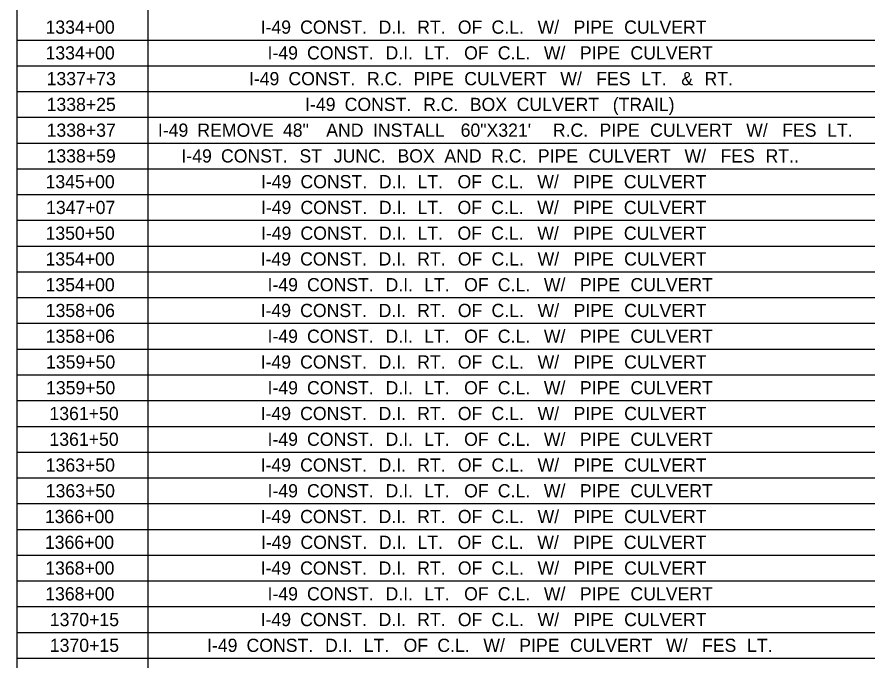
# Model space of a CAD drawing. Extents: x 1226564 to 1228153, y 151309 to 152340.
# Drawn here: x 1226563.6 to 1226838.2, y 151749.1 to 151956.8 of the extents above; entities that cross this region are included whole.
import ezdxf

# ---------------------------------------------------------------- set-up
doc = ezdxf.new("R2010")
doc.units = 0
doc.layers.add('R_Dimension', color=7, linetype='Continuous')

msp = doc.modelspace()

# ---------------------------------------------------------------- linework, layer by layer
at = {"layer": 'R_Dimension'}
for p, q in [((1226563.55, 151354.44), (1226563.55, 152160.49)), ((1226605.93, 151369.4), (1226605.93, 152160.49)), ((1226563.55, 151949.42), (1228152.75, 151949.42)), ((1226563.55, 151941.11), (1228152.75, 151941.11)), ((1226563.55, 151932.8), (1228152.75, 151932.8)), ((1226563.55, 151924.49), (1228152.75, 151924.49)), ((1226563.55, 151916.18), (1228152.75, 151916.18)), ((1226563.55, 151907.87), (1228152.75, 151907.87)), ((1226563.55, 151899.56), (1228152.75, 151899.56)), ((1226563.55, 151891.25), (1228152.75, 151891.25)), ((1226563.55, 151882.94), (1228152.75, 151882.94)), ((1226563.55, 151874.64), (1228152.75, 151874.64)), ((1226563.55, 151866.33), (1228152.75, 151866.33)), ((1226563.55, 151858.02), (1228152.75, 151858.02)), ((1226563.55, 151849.71), (1228152.75, 151849.71)), ((1226563.55, 151841.4), (1228152.75, 151841.4)), ((1226563.55, 151833.09), (1228152.75, 151833.09)), ((1226563.55, 151824.78), (1228152.75, 151824.78)), ((1226563.55, 151816.47), (1228152.75, 151816.47)), ((1226563.55, 151808.16), (1228152.75, 151808.16)), ((1226563.55, 151799.85), (1228152.75, 151799.85)), ((1226563.55, 151791.54), (1228152.75, 151791.54)), ((1226563.55, 151783.23), (1228152.75, 151783.23)), ((1226563.55, 151774.92), (1228152.75, 151774.92)), ((1226563.55, 151766.61), (1228152.75, 151766.61)), ((1226563.55, 151758.3), (1228152.75, 151758.3)), ((1226563.55, 151749.99), (1228152.75, 151749.99))]:
    msp.add_line(p, q, dxfattribs=at)

# ---------------------------------------------------------------- texts
for s, p in [('1334+00', (1226572.75, 151951.45)), ('I-49', (1226642.19, 151951.45)), (' CONST.', (1226653.36, 151951.45)), (' D.I.', (1226678.69, 151951.45)), (' RT.', (1226691.14, 151951.45)), (' OF', (1226704.26, 151951.45)), (' C.L.', (1226715.13, 151951.45)), (' W/', (1226730, 151951.45)), (' PIPE', (1226741.61, 151951.45)), (' CULVERT', (1226757.95, 151951.45)), ('1334+00', (1226572.75, 151943.14)), ('I-49', (1226644.42, 151943.14)), (' CONST.', (1226655.59, 151943.14)), (' D.I.', (1226680.93, 151943.14)), (' LT.', (1226693.37, 151943.14)), (' OF', (1226706.29, 151943.14)), (' C.L.', (1226717.16, 151943.14)), (' W/', (1226732.03, 151943.14)), (' PIPE', (1226743.64, 151943.14)), (' CULVERT', (1226759.98, 151943.14)), ('1337+73', (1226573.1, 151934.83)), ('I-49', (1226638.41, 151934.83)), (' CONST.', (1226649.59, 151934.83)), (' R.C.', (1226674.92, 151934.83)), (' PIPE', (1226689.99, 151934.83)), (' CULVERT', (1226706.33, 151934.83)), (' W/', (1226737.33, 151934.83)), (' FES', (1226748.94, 151934.83)), (' LT.', (1226763.47, 151934.83)), (' &', (1226776.39, 151934.83)), (' RT.', (1226783.87, 151934.83)), ('1338+25', (1226573.1, 151926.52)), ('I-49', (1226656.55, 151926.52)), (' CONST.', (1226667.72, 151926.52)), (' R.C.', (1226693.06, 151926.52)), (' BOX', (1226708.12, 151926.52)), (' CULVERT', (1226723.25, 151926.52)), (' (TRAIL)', (1226754.26, 151926.52)), ('1338+37', (1226573.1, 151918.21)), ('I-49', (1226609.02, 151918.21)), (' REMOVE', (1226620.19, 151918.21)), (' 48"', (1226647.81, 151918.21)), (' AND', (1226661.77, 151918.21)), (' INSTALL', (1226676.87, 151918.21)), (' 60"X321\'', (1226705.16, 151918.21)), (' R.C.', (1226734.92, 151918.21)), (' PIPE', (1226749.98, 151918.21)), (' CULVERT', (1226766.33, 151918.21)), (' W/', (1226797.33, 151918.21)), (' FES', (1226808.94, 151918.21)), (' LT.', (1226823.47, 151918.21)), ('1338+59', (1226573.08, 151909.9)), ('I-49', (1226616.63, 151909.9)), (' CONST.', (1226627.81, 151909.9)), (' ST', (1226653.14, 151909.9)), (' JUNC.', (1226664.22, 151909.9)), (' BOX', (1226684.78, 151909.9)), (' AND', (1226699.92, 151909.9)), (' R.C.', (1226715.02, 151909.9)), (' PIPE', (1226730.08, 151909.9)), (' CULVERT', (1226746.42, 151909.9)), (' W/', (1226777.43, 151909.9)), (' FES', (1226789.04, 151909.9)), (' RT..', (1226803.57, 151909.9)), ('1345+00', (1226572.75, 151901.59)), ('I-49', (1226642.29, 151901.59)), (' CONST.', (1226653.46, 151901.59)), (' D.I.', (1226678.79, 151901.59)), (' LT.', (1226691.24, 151901.59)), (' OF', (1226704.16, 151901.59)), (' C.L.', (1226715.03, 151901.59)), (' W/', (1226729.9, 151901.59)), (' PIPE', (1226741.51, 151901.59)), (' CULVERT', (1226757.85, 151901.59)), ('1347+07', (1226572.93, 151893.28)), ('I-49', (1226642.29, 151893.28)), (' CONST.', (1226653.46, 151893.28)), (' D.I.', (1226678.79, 151893.28)), (' LT.', (1226691.24, 151893.28)), (' OF', (1226704.16, 151893.28)), (' C.L.', (1226715.03, 151893.28)), (' W/', (1226729.9, 151893.28)), (' PIPE', (1226741.51, 151893.28)), (' CULVERT', (1226757.85, 151893.28)), ('1350+50', (1226572.75, 151884.97)), ('I-49', (1226642.29, 151884.97)), (' CONST.', (1226653.46, 151884.97)), (' OF', (1226704.16, 151884.97)), (' C.L.', (1226715.03, 151884.97)), (' W/', (1226729.9, 151884.97)), (' CULVERT', (1226757.85, 151884.97)), (' D.I.', (1226678.79, 151884.97)), (' LT.', (1226691.24, 151884.97)), (' PIPE', (1226741.51, 151884.97)), (' W/', (1226730, 151876.66)), ('1354+00', (1226572.75, 151876.66)), ('I-49', (1226642.19, 151876.66)), (' CONST.', (1226653.36, 151876.66)), (' D.I.', (1226678.69, 151876.66)), (' RT.', (1226691.14, 151876.66)), (' OF', (1226704.26, 151876.66)), (' C.L.', (1226715.13, 151876.66)), (' PIPE', (1226741.61, 151876.66)), (' CULVERT', (1226757.95, 151876.66)), (' W/', (1226732.03, 151868.35)), ('1354+00', (1226572.75, 151868.35)), ('I-49', (1226644.42, 151868.35)), (' CONST.', (1226655.59, 151868.35)), (' D.I.', (1226680.93, 151868.35)), (' LT.', (1226693.37, 151868.35)), (' OF', (1226706.29, 151868.35)), (' C.L.', (1226717.16, 151868.35)), (' PIPE', (1226743.64, 151868.35)), (' CULVERT', (1226759.98, 151868.35)), ('1358+06', (1226572.82, 151860.04)), ('I-49', (1226642.19, 151860.04)), (' CONST.', (1226653.36, 151860.04)), (' D.I.', (1226678.69, 151860.04)), (' RT.', (1226691.14, 151860.04)), (' OF', (1226704.26, 151860.04)), (' C.L.', (1226715.13, 151860.04)), (' W/', (1226730, 151860.04)), (' PIPE', (1226741.61, 151860.04)), (' CULVERT', (1226757.95, 151860.04)), ('1358+06', (1226572.82, 151851.73)), ('I-49', (1226644.42, 151851.73)), (' CONST.', (1226655.59, 151851.73)), (' D.I.', (1226680.93, 151851.73)), (' LT.', (1226693.37, 151851.73)), (' OF', (1226706.29, 151851.73)), (' C.L.', (1226717.16, 151851.73)), (' W/', (1226732.03, 151851.73)), (' PIPE', (1226743.64, 151851.73)), (' CULVERT', (1226759.98, 151851.73)), ('1359+50', (1226572.92, 151843.42)), ('I-49', (1226642.19, 151843.42)), (' CONST.', (1226653.36, 151843.42)), (' D.I.', (1226678.69, 151843.42)), (' RT.', (1226691.14, 151843.42)), (' OF', (1226704.26, 151843.42)), (' C.L.', (1226715.13, 151843.42)), (' W/', (1226730, 151843.42)), (' PIPE', (1226741.61, 151843.42)), (' CULVERT', (1226757.95, 151843.42)), ('1359+50', (1226572.92, 151835.11)), ('I-49', (1226644.42, 151835.11)), (' CONST.', (1226655.59, 151835.11)), (' D.I.', (1226680.93, 151835.11)), (' LT.', (1226693.37, 151835.11)), (' OF', (1226706.29, 151835.11)), (' C.L.', (1226717.16, 151835.11)), (' W/', (1226732.03, 151835.11)), (' PIPE', (1226743.64, 151835.11)), (' CULVERT', (1226759.98, 151835.11)), ('1361+50', (1226574.02, 151826.8)), ('I-49', (1226642.19, 151826.8)), (' CONST.', (1226653.36, 151826.8)), (' D.I.', (1226678.69, 151826.8)), (' RT.', (1226691.14, 151826.8)), (' OF', (1226704.26, 151826.8)), (' C.L.', (1226715.13, 151826.8)), (' W/', (1226730, 151826.8)), (' PIPE', (1226741.61, 151826.8)), (' CULVERT', (1226757.95, 151826.8)), ('1361+50', (1226574.02, 151818.49)), ('I-49', (1226644.42, 151818.49)), (' CONST.', (1226655.59, 151818.49)), (' D.I.', (1226680.93, 151818.49)), (' LT.', (1226693.37, 151818.49)), (' OF', (1226706.29, 151818.49)), (' C.L.', (1226717.16, 151818.49)), (' W/', (1226732.03, 151818.49)), (' PIPE', (1226743.64, 151818.49)), (' CULVERT', (1226759.98, 151818.49)), ('1363+50', (1226572.82, 151810.18)), ('I-49', (1226642.19, 151810.18)), (' CONST.', (1226653.36, 151810.18)), (' D.I.', (1226678.69, 151810.18)), (' RT.', (1226691.14, 151810.18)), (' OF', (1226704.26, 151810.18)), (' C.L.', (1226715.13, 151810.18)), (' W/', (1226730, 151810.18)), (' PIPE', (1226741.61, 151810.18)), (' CULVERT', (1226757.95, 151810.18)), ('1363+50', (1226572.82, 151801.87)), ('I-49', (1226644.42, 151801.87)), (' CONST.', (1226655.59, 151801.87)), (' D.I.', (1226680.93, 151801.87)), (' LT.', (1226693.37, 151801.87)), (' OF', (1226706.29, 151801.87)), (' C.L.', (1226717.16, 151801.87)), (' W/', (1226732.03, 151801.87)), (' PIPE', (1226743.64, 151801.87)), (' CULVERT', (1226759.98, 151801.87)), ('1366+00', (1226572.55, 151793.56)), ('I-49', (1226642.19, 151793.56)), (' CONST.', (1226653.36, 151793.56)), (' D.I.', (1226678.69, 151793.56)), (' RT.', (1226691.14, 151793.56)), (' OF', (1226704.26, 151793.56)), (' C.L.', (1226715.13, 151793.56)), (' W/', (1226730, 151793.56)), (' PIPE', (1226741.61, 151793.56)), (' CULVERT', (1226757.95, 151793.56)), ('1366+00', (1226572.55, 151785.25)), ('I-49', (1226642.29, 151785.25)), (' CONST.', (1226653.46, 151785.25)), (' D.I.', (1226678.79, 151785.25)), (' LT.', (1226691.24, 151785.25)), (' OF', (1226704.16, 151785.25)), (' C.L.', (1226715.03, 151785.25)), (' W/', (1226729.9, 151785.25)), (' PIPE', (1226741.51, 151785.25)), (' CULVERT', (1226757.85, 151785.25)), ('1368+00', (1226572.65, 151776.94)), ('I-49', (1226642.19, 151776.94)), (' CONST.', (1226653.36, 151776.94)), (' D.I.', (1226678.69, 151776.94)), (' RT.', (1226691.14, 151776.94)), (' OF', (1226704.26, 151776.94)), (' C.L.', (1226715.13, 151776.94)), (' W/', (1226730, 151776.94)), (' PIPE', (1226741.61, 151776.94)), (' CULVERT', (1226757.95, 151776.94)), ('1368+00', (1226572.65, 151768.63)), ('I-49', (1226644.42, 151768.63)), (' CONST.', (1226655.59, 151768.63)), (' D.I.', (1226680.93, 151768.63)), (' LT.', (1226693.37, 151768.63)), (' OF', (1226706.29, 151768.63)), (' C.L.', (1226717.16, 151768.63)), (' W/', (1226732.03, 151768.63)), (' PIPE', (1226743.64, 151768.63)), (' CULVERT', (1226759.98, 151768.63)), ('1370+15', (1226574.14, 151760.32)), ('I-49', (1226642.19, 151760.32)), (' CONST.', (1226653.36, 151760.32)), (' D.I.', (1226678.69, 151760.32)), (' RT.', (1226691.14, 151760.32)), (' OF', (1226704.26, 151760.32)), (' C.L.', (1226715.13, 151760.32)), (' W/', (1226730, 151760.32)), (' PIPE', (1226741.61, 151760.32)), (' CULVERT', (1226757.95, 151760.32)), ('1370+15', (1226574.14, 151752.01)), ('I-49', (1226624.89, 151752.01)), (' CONST.', (1226636.06, 151752.01)), (' D.I.', (1226661.4, 151752.01)), (' LT.', (1226673.85, 151752.01)), (' OF', (1226686.76, 151752.01)), (' C.L.', (1226697.64, 151752.01)), (' W/', (1226712.5, 151752.01)), (' PIPE', (1226724.11, 151752.01)), (' CULVERT', (1226740.45, 151752.01)), (' W/', (1226771.46, 151752.01)), (' FES', (1226783.07, 151752.01)), (' LT.', (1226797.6, 151752.01))]:
    msp.add_text(s, height=4.261, dxfattribs=at).set_placement(p)

doc.saveas('drawing.dxf')
